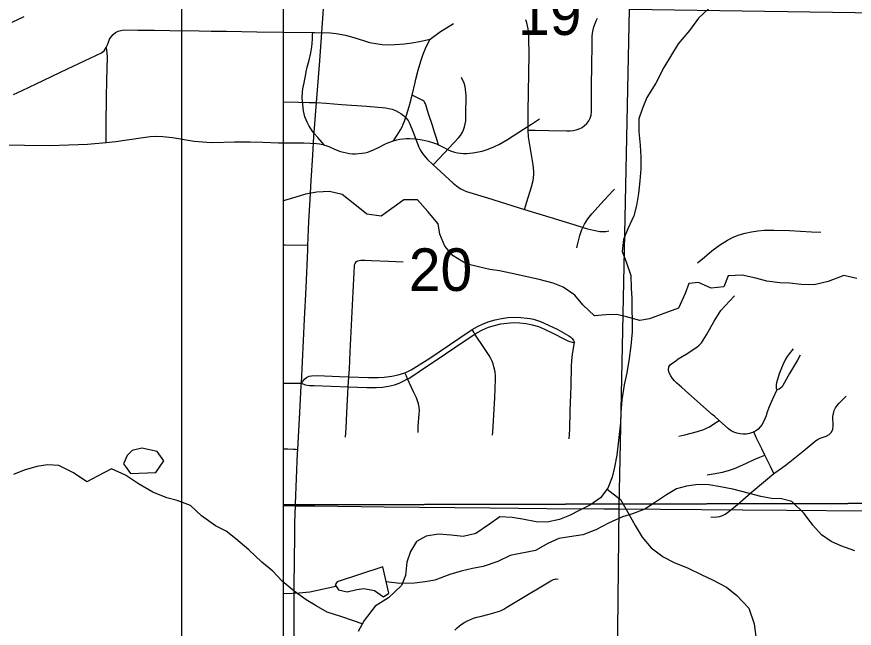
# Model space of a CAD drawing. Extents: x 0 to 34, y 0 to 22.
# Drawn here: x 12.978 to 13.802, y 16.121 to 16.722 of the extents above; entities that cross this region are included whole.
import ezdxf

# ---------------------------------------------------------------- set-up
doc = ezdxf.new("R2010")
doc.units = 0
for name, color, linetype in [('GM_X_City_Street', 7, 'Continuous'), ('GM_X_Corporation', 7, 'Continuous'), ('GM_X_County_Road', 7, 'Continuous'), ('GM_X_Minor_Lake', 7, 'Continuous'), ('GM_X_Minor_River', 7, 'Continuous'), ('GM_X_Rail_Line', 7, 'Continuous'), ('GM_X_Section_Text', 7, 'Continuous'), ('GM_X_US_Route', 7, 'Continuous'), ('GM_X_US_Shield', 7, 'Continuous'), ('SH_Data', 7, 'Continuous')]:
    doc.layers.add(name, color=color, linetype=linetype)

msp = doc.modelspace()

# ---------------------------------------------------------------- linework, layer by layer
at = {"layer": 'GM_X_City_Street'}
for points in [[(13.38468, 16.70023), (13.39508, 16.7075), (13.40094, 16.71138), (13.40766, 16.71561)], [(13.47759, 16.53272), (13.4799, 16.54005), (13.48461, 16.55492), (13.48605, 16.56098), (13.48649, 16.56407), (13.48672, 16.56718), (13.48673, 16.57029), (13.4862, 16.5765), (13.48245, 16.59801), (13.48169, 16.60419), (13.48133, 16.61068), (13.48117, 16.61351), (13.48124, 16.62911), (13.48211, 16.68525), (13.48203, 16.70083), (13.48183, 16.70612), (13.48125, 16.71013), (13.47986, 16.71621), (13.47904, 16.71922)], [(13.48133, 16.61068), (13.48823, 16.61061), (13.50139, 16.61037), (13.51926, 16.61005), (13.52237, 16.61006), (13.52546, 16.61031), (13.52851, 16.61091), (13.53147, 16.61183), (13.53424, 16.61322), (13.53674, 16.61507), (13.53894, 16.61725), (13.54077, 16.61975), (13.54217, 16.62252), (13.54309, 16.62548), (13.54345, 16.62856), (13.54368, 16.6565), (13.54386, 16.67204), (13.5441, 16.69687), (13.5443, 16.70307), (13.5446, 16.70615), (13.54512, 16.7092), (13.54589, 16.7122), (13.54806, 16.71802), (13.54935, 16.72084)], [(12.97516, 16.64553), (12.98353, 16.64951), (12.99744, 16.65614), (13.028, 16.67103), (13.03912, 16.67615), (13.05593, 16.68397), (13.06163, 16.68665), (13.06426, 16.68871), (13.06533, 16.69019), (13.06632, 16.69185), (13.06731, 16.69445), (13.0683, 16.69729), (13.06957, 16.69999), (13.07118, 16.7025), (13.07308, 16.70474), (13.07535, 16.70657), (13.07793, 16.70791), (13.08073, 16.70867), (13.0836, 16.70914), (13.09719, 16.70896), (13.10412, 16.70896), (13.1137, 16.7088), (13.12888, 16.70847), (13.1576, 16.70813), (13.16932, 16.70796), (13.18462, 16.70798), (13.21422, 16.70747), (13.24007, 16.70704), (13.26934, 16.7067), (13.27098, 16.70668), (13.28641, 16.70624), (13.29253, 16.70565), (13.30159, 16.70407), (13.30753, 16.70255), (13.31925, 16.69864), (13.32527, 16.69692), (13.33143, 16.69571), (13.33765, 16.69493), (13.3439, 16.69462), (13.35015, 16.69469), (13.35951, 16.69539), (13.36694, 16.69636), (13.37444, 16.69792), (13.38468, 16.70023)], [(13.28104, 16.59595), (13.27875, 16.59852), (13.27446, 16.60332), (13.27075, 16.60738), (13.26885, 16.60984), (13.26554, 16.61512), (13.26408, 16.61788), (13.26281, 16.62072), (13.26172, 16.62366), (13.26086, 16.62665), (13.26022, 16.62966), (13.25944, 16.63577), (13.25909, 16.64199), (13.25934, 16.64819), (13.25966, 16.65129), (13.26019, 16.65434), (13.26089, 16.65732), (13.2615, 16.66083), (13.26216, 16.66381), (13.26282, 16.6681), (13.26393, 16.67243), (13.26596, 16.67932), (13.26739, 16.6867), (13.26854, 16.69249), (13.26893, 16.69599), (13.2691, 16.70028), (13.26926, 16.70458), (13.26934, 16.7067)], [(13.34882, 16.60014), (13.3524, 16.60582), (13.35569, 16.61105), (13.35713, 16.61378), (13.3584, 16.61659), (13.35952, 16.61946), (13.36149, 16.62525), (13.3641, 16.63398), (13.36573, 16.63979), (13.36649, 16.64274), (13.36703, 16.64498), (13.37007, 16.65762), (13.37074, 16.66062), (13.37295, 16.66953), (13.37558, 16.67837), (13.37799, 16.68546), (13.38096, 16.69272), (13.38468, 16.70023)], [(13.06632, 16.59836), (13.06631, 16.60101), (13.06627, 16.61554), (13.06647, 16.64346), (13.06673, 16.65898), (13.06736, 16.68306), (13.06714, 16.68602), (13.06665, 16.68949), (13.06632, 16.69185)], [(13.38768, 16.57665), (13.39355, 16.58284), (13.41272, 16.60302), (13.41464, 16.60544), (13.41627, 16.60807), (13.41759, 16.61086), (13.41861, 16.61378), (13.41933, 16.61678), (13.41976, 16.61985), (13.42002, 16.62602), (13.4201, 16.64459), (13.41996, 16.64767), (13.41963, 16.65074), (13.41921, 16.65366), (13.41815, 16.65672), (13.41574, 16.66241)], [(13.39307, 16.59618), (13.39067, 16.60382), (13.38886, 16.60956), (13.38708, 16.61534), (13.38332, 16.62674), (13.38155, 16.63231), (13.38091, 16.63467), (13.38028, 16.63637), (13.37964, 16.63764), (13.37911, 16.63836), (13.37851, 16.639), (13.37753, 16.63968), (13.37641, 16.64028), (13.37507, 16.64097), (13.36703, 16.64498)], [(13.2404, 16.63833), (13.25538, 16.638), (13.26591, 16.63792), (13.26781, 16.6379), (13.27305, 16.63786)], [(13.27305, 16.63786), (13.28253, 16.63728), (13.29006, 16.63662), (13.29758, 16.6359), (13.32249, 16.63423), (13.34117, 16.63255), (13.34434, 16.63205), (13.34746, 16.63112), (13.35065, 16.62989), (13.35361, 16.62841), (13.35603, 16.62691), (13.35864, 16.62498), (13.36102, 16.62281), (13.36307, 16.62021), (13.36455, 16.61734), (13.36801, 16.60856), (13.37358, 16.59405), (13.37492, 16.59132), (13.37649, 16.58872), (13.37826, 16.58624), (13.38228, 16.58162), (13.38768, 16.57665), (13.3914, 16.57321), (13.40759, 16.55855), (13.41241, 16.55473), (13.41496, 16.55307), (13.41763, 16.55163), (13.42042, 16.55046), (13.4412, 16.54398), (13.47759, 16.53272), (13.49486, 16.52738), (13.52175, 16.51921), (13.53961, 16.51369), (13.5456, 16.51216), (13.55163, 16.51111), (13.55465, 16.51093), (13.55764, 16.51109), (13.56062, 16.51164)], [(12.96169, 16.59612), (12.98586, 16.59581), (13.01067, 16.5957), (13.02928, 16.59612), (13.04786, 16.59688), (13.06632, 16.59836), (13.0756, 16.59947), (13.10015, 16.6031), (13.10945, 16.60433), (13.11572, 16.60465), (13.12199, 16.60447), (13.13131, 16.60351), (13.15277, 16.59993), (13.16507, 16.59872), (13.17118, 16.59849), (13.19239, 16.59921), (13.20787, 16.59907), (13.22027, 16.59866), (13.2356, 16.59818), (13.26045, 16.59801), (13.2729, 16.59758), (13.27604, 16.59726), (13.27913, 16.59653), (13.28104, 16.59595), (13.28217, 16.59561), (13.28513, 16.59447), (13.29078, 16.59189), (13.29649, 16.58975), (13.30242, 16.58826), (13.30544, 16.58773), (13.30846, 16.58741), (13.31147, 16.58735), (13.31753, 16.58785), (13.32052, 16.58838), (13.32346, 16.58912), (13.3292, 16.59116), (13.33468, 16.59386), (13.34019, 16.59678), (13.34307, 16.59807), (13.34882, 16.60014), (13.35194, 16.60106), (13.35506, 16.6017), (13.35818, 16.60215), (13.36131, 16.60242), (13.36445, 16.60249), (13.37071, 16.602), (13.3769, 16.60101), (13.38301, 16.59965), (13.38903, 16.59783), (13.39197, 16.59672), (13.39307, 16.59618), (13.39761, 16.59392), (13.40307, 16.59109), (13.40586, 16.58992), (13.40873, 16.589), (13.41167, 16.58831), (13.41467, 16.58786), (13.4177, 16.58763), (13.42074, 16.58762), (13.42682, 16.58818), (13.43586, 16.59003), (13.44172, 16.5918), (13.44741, 16.5941), (13.45297, 16.59676), (13.46096, 16.6014), (13.47659, 16.61155), (13.48438, 16.61663), (13.49234, 16.62184)], [(13.52903, 16.49482), (13.52977, 16.49788), (13.53205, 16.50694), (13.53404, 16.51279), (13.53671, 16.51832), (13.54006, 16.52349), (13.54387, 16.52839), (13.55589, 16.54179), (13.56492, 16.5513), (13.56619, 16.55263)], [(13.64781, 16.48021), (13.65458, 16.48589), (13.66178, 16.49193), (13.6694, 16.49742), (13.67726, 16.50256), (13.68285, 16.50552), (13.68874, 16.50779), (13.69482, 16.50947), (13.70097, 16.51072), (13.70718, 16.51161), (13.71342, 16.51213), (13.72278, 16.51229), (13.73833, 16.51181), (13.75993, 16.5106), (13.76917, 16.51032)], [(13.2404, 16.49782), (13.24208, 16.49778), (13.26378, 16.49739), (13.26459, 16.49737)], [(13.30426, 16.35836), (13.30487, 16.36822), (13.30538, 16.37577), (13.3062, 16.39264), (13.30903, 16.45176), (13.30994, 16.47066), (13.31033, 16.47731), (13.31044, 16.47804), (13.31065, 16.47872), (13.31093, 16.4794), (13.31167, 16.48039), (13.31253, 16.48137), (13.31365, 16.48211), (13.31494, 16.48255), (13.31666, 16.4828), (13.32087, 16.48277), (13.32721, 16.48252), (13.34397, 16.48169), (13.35814, 16.481)], [(13.7257, 16.35521), (13.72148, 16.34602), (13.71818, 16.33844), (13.7161, 16.33262), (13.71523, 16.32965), (13.71414, 16.32675), (13.71122, 16.3213), (13.70945, 16.31876), (13.7073, 16.31654), (13.70478, 16.31473), (13.70302, 16.31386), (13.70195, 16.31334), (13.69892, 16.31235), (13.6958, 16.31178), (13.69266, 16.31159), (13.68959, 16.31194), (13.68659, 16.3127), (13.68366, 16.31371), (13.68088, 16.31505), (13.67836, 16.31684), (13.66906, 16.32517), (13.66452, 16.32923), (13.66208, 16.33107), (13.63897, 16.35172), (13.632, 16.35786), (13.62729, 16.36187), (13.62512, 16.36407), (13.62317, 16.36647), (13.62146, 16.36909), (13.62006, 16.37192), (13.61924, 16.37489), (13.61951, 16.37783), (13.62127, 16.38018), (13.6263, 16.38388), (13.62884, 16.38563), (13.63676, 16.39046), (13.64703, 16.39737), (13.64942, 16.39934), (13.65159, 16.40152), (13.65346, 16.40398), (13.65664, 16.4093), (13.66411, 16.42285), (13.66729, 16.42815), (13.67087, 16.43318), (13.67493, 16.43786), (13.67915, 16.44238), (13.68401, 16.44759)], [(13.25817, 16.36185), (13.26125, 16.36582), (13.26336, 16.36757), (13.26569, 16.36874), (13.26814, 16.3692), (13.27375, 16.36944), (13.29572, 16.36855), (13.30487, 16.36822), (13.32429, 16.36751), (13.33354, 16.36737), (13.33967, 16.36782), (13.34715, 16.36879), (13.35339, 16.37008), (13.35992, 16.37212), (13.36348, 16.37367), (13.36621, 16.375), (13.36888, 16.37651), (13.38454, 16.38657), (13.41288, 16.40578), (13.42602, 16.41447), (13.43132, 16.41753), (13.43701, 16.42023), (13.4429, 16.42244), (13.44892, 16.42421), (13.45506, 16.42552), (13.46128, 16.42643), (13.4676, 16.4267), (13.47402, 16.42656), (13.48024, 16.42589), (13.4832, 16.4254), (13.4864, 16.42466), (13.49331, 16.42244), (13.50121, 16.41899), (13.50959, 16.41479), (13.52131, 16.40828), (13.52305, 16.40702), (13.52453, 16.40565), (13.52589, 16.4038), (13.52694, 16.40177)], [(13.25817, 16.36185), (13.26184, 16.36033), (13.26615, 16.35964), (13.27071, 16.35962), (13.30426, 16.35836), (13.32244, 16.35768), (13.3317, 16.35754), (13.33779, 16.3579), (13.34382, 16.3588), (13.34962, 16.36016), (13.35438, 16.3617), (13.35832, 16.36376), (13.3627, 16.36606), (13.3637, 16.36659), (13.37404, 16.37333), (13.39977, 16.39067), (13.42032, 16.4046), (13.42892, 16.4101), (13.43079, 16.4113), (13.43632, 16.41428), (13.44208, 16.41676), (13.44806, 16.41865), (13.45418, 16.42004), (13.46038, 16.42095), (13.46664, 16.42136), (13.47291, 16.4212), (13.47915, 16.42046), (13.4853, 16.41921), (13.49134, 16.41749), (13.49726, 16.41504), (13.50556, 16.41099), (13.51763, 16.40482), (13.52009, 16.40356), (13.52219, 16.4027), (13.52441, 16.40208), (13.52694, 16.40177)], [(13.44619, 16.31068), (13.44641, 16.31375), (13.44846, 16.34749), (13.44919, 16.36589), (13.44904, 16.36889), (13.44861, 16.37304), (13.44761, 16.37787), (13.44682, 16.38077), (13.44579, 16.38356), (13.4445, 16.38626), (13.443, 16.3889), (13.43829, 16.396), (13.42892, 16.4101), (13.42765, 16.41202), (13.42602, 16.41447)], [(13.52164, 16.30698), (13.52222, 16.31625), (13.52262, 16.33481), (13.52332, 16.35028), (13.52353, 16.35955), (13.52381, 16.37808), (13.52413, 16.38424), (13.52485, 16.39039), (13.52694, 16.40177)], [(13.74175, 16.39565), (13.73792, 16.39061), (13.73602, 16.38812), (13.73439, 16.38547), (13.73161, 16.3799), (13.72819, 16.37118), (13.72533, 16.36227), (13.72506, 16.36044), (13.72506, 16.35865), (13.72525, 16.357), (13.7257, 16.35521)], [(13.74877, 16.38938), (13.746, 16.38455), (13.73836, 16.37126), (13.73175, 16.3594), (13.73093, 16.35814), (13.72952, 16.35686), (13.728, 16.35604), (13.7257, 16.35521)], [(13.37307, 16.31325), (13.37291, 16.31631), (13.37295, 16.31939), (13.37416, 16.33184), (13.37419, 16.33505), (13.37392, 16.33825), (13.37334, 16.34142), (13.37241, 16.3445), (13.37126, 16.34748), (13.3686, 16.35319), (13.3627, 16.36606), (13.36153, 16.3686), (13.35992, 16.37212)], [(13.2404, 16.36185), (13.24689, 16.36185), (13.25588, 16.36185), (13.25817, 16.36185)], [(13.30158, 16.30862), (13.30226, 16.31769), (13.30282, 16.3328), (13.30426, 16.35836)], [(13.723, 16.27305), (13.73033, 16.27814), (13.73525, 16.2818), (13.75164, 16.29506), (13.7635, 16.30478), (13.76594, 16.30647), (13.76844, 16.3078), (13.77439, 16.30965), (13.77726, 16.31124), (13.77953, 16.31369), (13.78074, 16.31672), (13.78114, 16.31995), (13.78096, 16.32918), (13.78138, 16.33208), (13.78223, 16.33484), (13.78352, 16.33746), (13.78517, 16.33993), (13.78709, 16.34222), (13.78922, 16.3443), (13.79399, 16.34895)], [(13.62927, 16.30964), (13.63546, 16.31114), (13.64785, 16.31416), (13.65387, 16.31617), (13.65678, 16.31744), (13.65957, 16.31897), (13.6649, 16.32245), (13.66906, 16.32517)], [(13.723, 16.27305), (13.71975, 16.27939), (13.71411, 16.29094), (13.71114, 16.29724), (13.70562, 16.30853), (13.70302, 16.31386)], [(13.2404, 16.29727), (13.24498, 16.29718), (13.25053, 16.29699), (13.25245, 16.29689), (13.25453, 16.29663)], [(13.65715, 16.27186), (13.66315, 16.27282), (13.67229, 16.27429), (13.67826, 16.27591), (13.68403, 16.27803), (13.69531, 16.2829), (13.70366, 16.28664), (13.70924, 16.28894), (13.71411, 16.29094)], [(13.6608, 16.23003), (13.66682, 16.23035), (13.66974, 16.2308), (13.6725, 16.23164), (13.67503, 16.23295), (13.67744, 16.23463), (13.68677, 16.24234), (13.7007, 16.25436), (13.71458, 16.26623), (13.723, 16.27305)], [(13.40922, 16.11898), (13.41142, 16.12117), (13.41377, 16.12322), (13.41625, 16.1251), (13.41887, 16.1268), (13.4216, 16.12828), (13.42438, 16.12954), (13.42746, 16.13064), (13.43067, 16.13163), (13.43412, 16.13237), (13.44275, 16.13459), (13.44744, 16.13595), (13.45161, 16.13725), (13.45312, 16.13779), (13.45454, 16.1384), (13.45713, 16.13971), (13.46008, 16.14144), (13.47667, 16.15141), (13.49697, 16.16362), (13.50352, 16.16755), (13.50622, 16.16881), (13.50776, 16.16924), (13.50853, 16.1694), (13.51059, 16.16924)]]:
    msp.add_lwpolyline(points, dxfattribs=at)
at = {"layer": 'GM_X_Corporation'}
msp.add_lwpolyline([(13.2404, 19.74462), (13.2404, 15.59448), (13.24851, 15.59444), (13.24868, 15.6513), (13.24921, 15.72689), (13.56503, 15.72552), (13.57075, 16.24037), (13.58078, 16.72959), (14.57912, 16.71489), (14.56987, 16.29926), (14.56992, 16.29412), (14.62699, 16.29675)], dxfattribs=at)
at = {"layer": 'GM_X_County_Road'}
for points in [[(13.27305, 16.63786), (13.2762, 16.67881), (13.27962, 16.7253), (13.28049, 16.73924)], [(13.26459, 16.49737), (13.26553, 16.52083), (13.26685, 16.54252), (13.26795, 16.56113), (13.26942, 16.58591), (13.27049, 16.6045), (13.27305, 16.63786)], [(13.25817, 16.36185), (13.26125, 16.42465), (13.26274, 16.45568), (13.26441, 16.49293), (13.26459, 16.49737)], [(13.25453, 16.29663), (13.25532, 16.30897), (13.25658, 16.3331), (13.25805, 16.35948), (13.25817, 16.36185)], [(13.25227, 16.24134), (13.25233, 16.24335), (13.25338, 16.26814), (13.25432, 16.293), (13.25453, 16.29663)], [(13.25091, 16.07534), (13.25102, 16.10848), (13.25115, 16.13261), (13.25122, 16.14569), (13.25101, 16.16116), (13.25133, 16.18852), (13.25159, 16.21105), (13.25176, 16.22472), (13.25227, 16.24134)]]:
    msp.add_lwpolyline(points, dxfattribs=at)
at = {"layer": 'GM_X_Minor_Lake'}
for points in [[(13.09002, 16.273), (13.1151, 16.27405), (13.12273, 16.28543), (13.1163, 16.29457), (13.10111, 16.29804), (13.09161, 16.29579), (13.08666, 16.29087)], [(13.08666, 16.29087), (13.08312, 16.28245), (13.08507, 16.27985), (13.09002, 16.273)], [(13.33819, 16.18112), (13.29332, 16.16646), (13.29142, 16.16342), (13.29482, 16.15847), (13.30317, 16.15654), (13.31268, 16.15879), (13.31952, 16.1599), (13.33015, 16.15797), (13.33887, 16.15186), (13.3442, 16.15526)], [(13.3442, 16.15526), (13.33819, 16.18112)]]:
    msp.add_lwpolyline(points, dxfattribs=at)
at = {"layer": 'GM_X_Minor_River'}
for points in [[(13.66273, 16.73387), (13.64864, 16.72062), (13.63986, 16.70849), (13.62881, 16.69561), (13.62232, 16.68461), (13.61468, 16.6721), (13.60666, 16.65692), (13.59789, 16.64289), (13.59329, 16.63113), (13.59023, 16.62164), (13.59019, 16.6091), (13.59129, 16.59579), (13.59202, 16.58401), (13.59198, 16.57261), (13.59119, 16.56083), (13.58964, 16.54829), (13.5877, 16.53652), (13.58501, 16.52627), (13.57928, 16.51375), (13.57507, 16.50312), (13.57352, 16.49135), (13.57767, 16.48107), (13.58218, 16.46776), (13.58253, 16.45521), (13.58326, 16.44533), (13.58323, 16.43507), (13.58358, 16.42291), (13.58354, 16.41227), (13.58236, 16.39859), (13.58043, 16.38606), (13.57811, 16.37201), (13.5758, 16.36023), (13.57348, 16.34542), (13.5723, 16.33288), (13.57189, 16.323), (13.57033, 16.30857), (13.56838, 16.29109), (13.56607, 16.27932), (13.56376, 16.26945), (13.55955, 16.25844), (13.5523, 16.24897)], [(12.98532, 16.72217), (12.97352, 16.71651)], [(13.42034, 16.47915), (13.40745, 16.48718), (13.39911, 16.49671), (13.39421, 16.50851), (13.39272, 16.51839), (13.3825, 16.53059), (13.37227, 16.54202), (13.35897, 16.54207), (13.34946, 16.53526), (13.33652, 16.52619), (13.32247, 16.52814), (13.31223, 16.53615), (13.29821, 16.54722), (13.28568, 16.5503), (13.27352, 16.54959), (13.26212, 16.54773), (13.25262, 16.54472), (13.24159, 16.54134), (13.2404, 16.54116)], [(13.80437, 16.4649), (13.79184, 16.4676), (13.77625, 16.46195), (13.76256, 16.45858), (13.74965, 16.45901), (13.73825, 16.46019), (13.72876, 16.4606), (13.71585, 16.46216), (13.70522, 16.46524), (13.69155, 16.46795), (13.67787, 16.46723), (13.67366, 16.45661), (13.66112, 16.45513), (13.6486, 16.46088), (13.6391, 16.45977), (13.63565, 16.4499), (13.62915, 16.43548), (13.61204, 16.42946), (13.60063, 16.42494), (13.59113, 16.42346), (13.57784, 16.42692), (13.56835, 16.42923), (13.5581, 16.42889), (13.54632, 16.42817), (13.53495, 16.43885), (13.527, 16.44838), (13.51563, 16.4564), (13.50576, 16.46023), (13.49209, 16.4637), (13.464, 16.46988), (13.45299, 16.4722), (13.4435, 16.47375), (13.43249, 16.47607), (13.42034, 16.47915)], [(13.31802, 16.12506), (13.30957, 16.12821), (13.29705, 16.13243), (13.28339, 16.13666), (13.27277, 16.14278), (13.26291, 16.14889), (13.25115, 16.15729), (13.2394, 16.16721), (13.22993, 16.17713), (13.21932, 16.1859), (13.20644, 16.19811), (13.19356, 16.20879), (13.18408, 16.21643), (13.17383, 16.2214), (13.15981, 16.23133), (13.1492, 16.24163), (13.13592, 16.24662), (13.12567, 16.24893), (13.11201, 16.25468), (13.09797, 16.26271), (13.08508, 16.27149), (13.07142, 16.27762), (13.05772, 16.27045), (13.04707, 16.26479), (13.03418, 16.27357), (13.01976, 16.28084), (13.00837, 16.28164), (12.9981, 16.27978), (12.98556, 16.2764), (12.97491, 16.27188)], [(13.80247, 16.19699), (13.78881, 16.20198), (13.77932, 16.20619), (13.76984, 16.21268), (13.76113, 16.22221), (13.75281, 16.23364), (13.74068, 16.24547), (13.73043, 16.24816), (13.72056, 16.24858), (13.70993, 16.25051), (13.69892, 16.25321), (13.68259, 16.25745), (13.67044, 16.25977), (13.65905, 16.26171), (13.64842, 16.26213), (13.63701, 16.26065), (13.62713, 16.25802), (13.61723, 16.25197), (13.60543, 16.24404), (13.59592, 16.23799), (13.58375, 16.23347), (13.57387, 16.23046), (13.56017, 16.22405), (13.54762, 16.21763), (13.53507, 16.21274), (13.52176, 16.21089), (13.5115, 16.20902), (13.50047, 16.20412), (13.4883, 16.19732), (13.46359, 16.19247), (13.45141, 16.18643), (13.43696, 16.18154), (13.42632, 16.17968), (13.4153, 16.17705), (13.40427, 16.17367), (13.38944, 16.16802), (13.37994, 16.16654), (13.3693, 16.16505), (13.35486, 16.16472)], [(13.55889, 16.25757), (13.57205, 16.24738), (13.57999, 16.23367), (13.58642, 16.22186), (13.59322, 16.21044), (13.60231, 16.19977), (13.61406, 16.19099), (13.62468, 16.18563), (13.63872, 16.17988), (13.652, 16.17338), (13.66262, 16.1684), (13.67628, 16.16113), (13.68651, 16.15311), (13.69825, 16.14053), (13.70353, 16.12531), (13.70538, 16.1101), (13.70306, 16.09567), (13.70037, 16.08352), (13.6973, 16.07327), (13.69193, 16.05809), (13.6881, 16.04632), (13.68388, 16.03114), (13.68195, 16.02126), (13.6804, 16.01025)], [(13.5523, 16.24897), (13.54241, 16.24216), (13.53137, 16.2365), (13.52186, 16.23159), (13.51197, 16.22783), (13.49981, 16.22521), (13.48917, 16.22562), (13.4755, 16.22795), (13.46563, 16.22989), (13.45347, 16.23031), (13.4432, 16.22312), (13.42987, 16.21405), (13.41733, 16.21106), (13.40555, 16.21224), (13.39302, 16.21342), (13.38086, 16.21156), (13.37135, 16.20627), (13.36562, 16.19641), (13.36179, 16.18579), (13.36061, 16.17287), (13.35678, 16.163), (13.34383, 16.15089), (13.33089, 16.14257), (13.31983, 16.12855), (13.3141, 16.11755)], [(13.29216, 16.16191), (13.26632, 16.15629), (13.25607, 16.15519), (13.24315, 16.15485), (13.2404, 16.15494)], [(13.35486, 16.16472), (13.34162, 16.16638)]]:
    msp.add_lwpolyline(points, dxfattribs=at)
at = {"layer": 'GM_X_Rail_Line'}
msp.add_lwpolyline([(13.2404, 20.24939), (13.2404, 14.2201)], dxfattribs=at)
at = {"layer": 'GM_X_US_Route'}
msp.add_line((13.2404, 16.24146), (13.25227, 16.24134), dxfattribs=at)
for points in [[(13.57097, 16.23818), (13.69218, 16.23726), (13.73566, 16.23682), (13.81333, 16.23636), (13.89722, 16.23708), (13.95001, 16.23874), (14.00589, 16.2409), (14.04623, 16.24227), (14.07475, 16.24341), (14.08347, 16.24376), (14.23861, 16.24975), (14.32238, 16.25285), (14.46821, 16.25856), (14.51787, 16.26046), (14.55201, 16.26183), (14.58153, 16.26285), (14.67417, 16.26609)], [(13.25227, 16.24134), (13.27141, 16.24115), (13.33948, 16.24024), (13.44398, 16.23934), (13.49974, 16.23874), (13.55552, 16.23834), (13.57097, 16.23818)]]:
    msp.add_lwpolyline(points, dxfattribs=at)
at = {"layer": 'GM_X_US_Shield'}
for points in [[(13.2404, 17.23459), (13.2404, 16.24226), (14.07331, 16.24402), (14.08752, 17.22638)], [(13.2404, 16.24226), (13.2404, 15.22087), (14.06942, 15.21356), (14.07331, 16.24402)]]:
    msp.add_lwpolyline(points, close=True, dxfattribs=at)
at = {"layer": 'SH_Data'}
for p, q in [((13.1404, 21), (13.1404, 14)), ((13.2404, 20.9), (13.2404, 14.1))]:
    msp.add_line(p, q, dxfattribs=at)

# ---------------------------------------------------------------- texts
at = {"layer": 'GM_X_Section_Text'}
for s, p in [('19', (13.47138, 16.70423)), ('20', (13.36389, 16.45255))]:
    msp.add_text(s, height=0.041856, rotation=0.00001, dxfattribs=at).set_placement(p)

doc.saveas('drawing.dxf')
